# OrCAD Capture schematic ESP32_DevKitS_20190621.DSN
size C; title: ESP32-DevKitS-Board; rev: 0.1
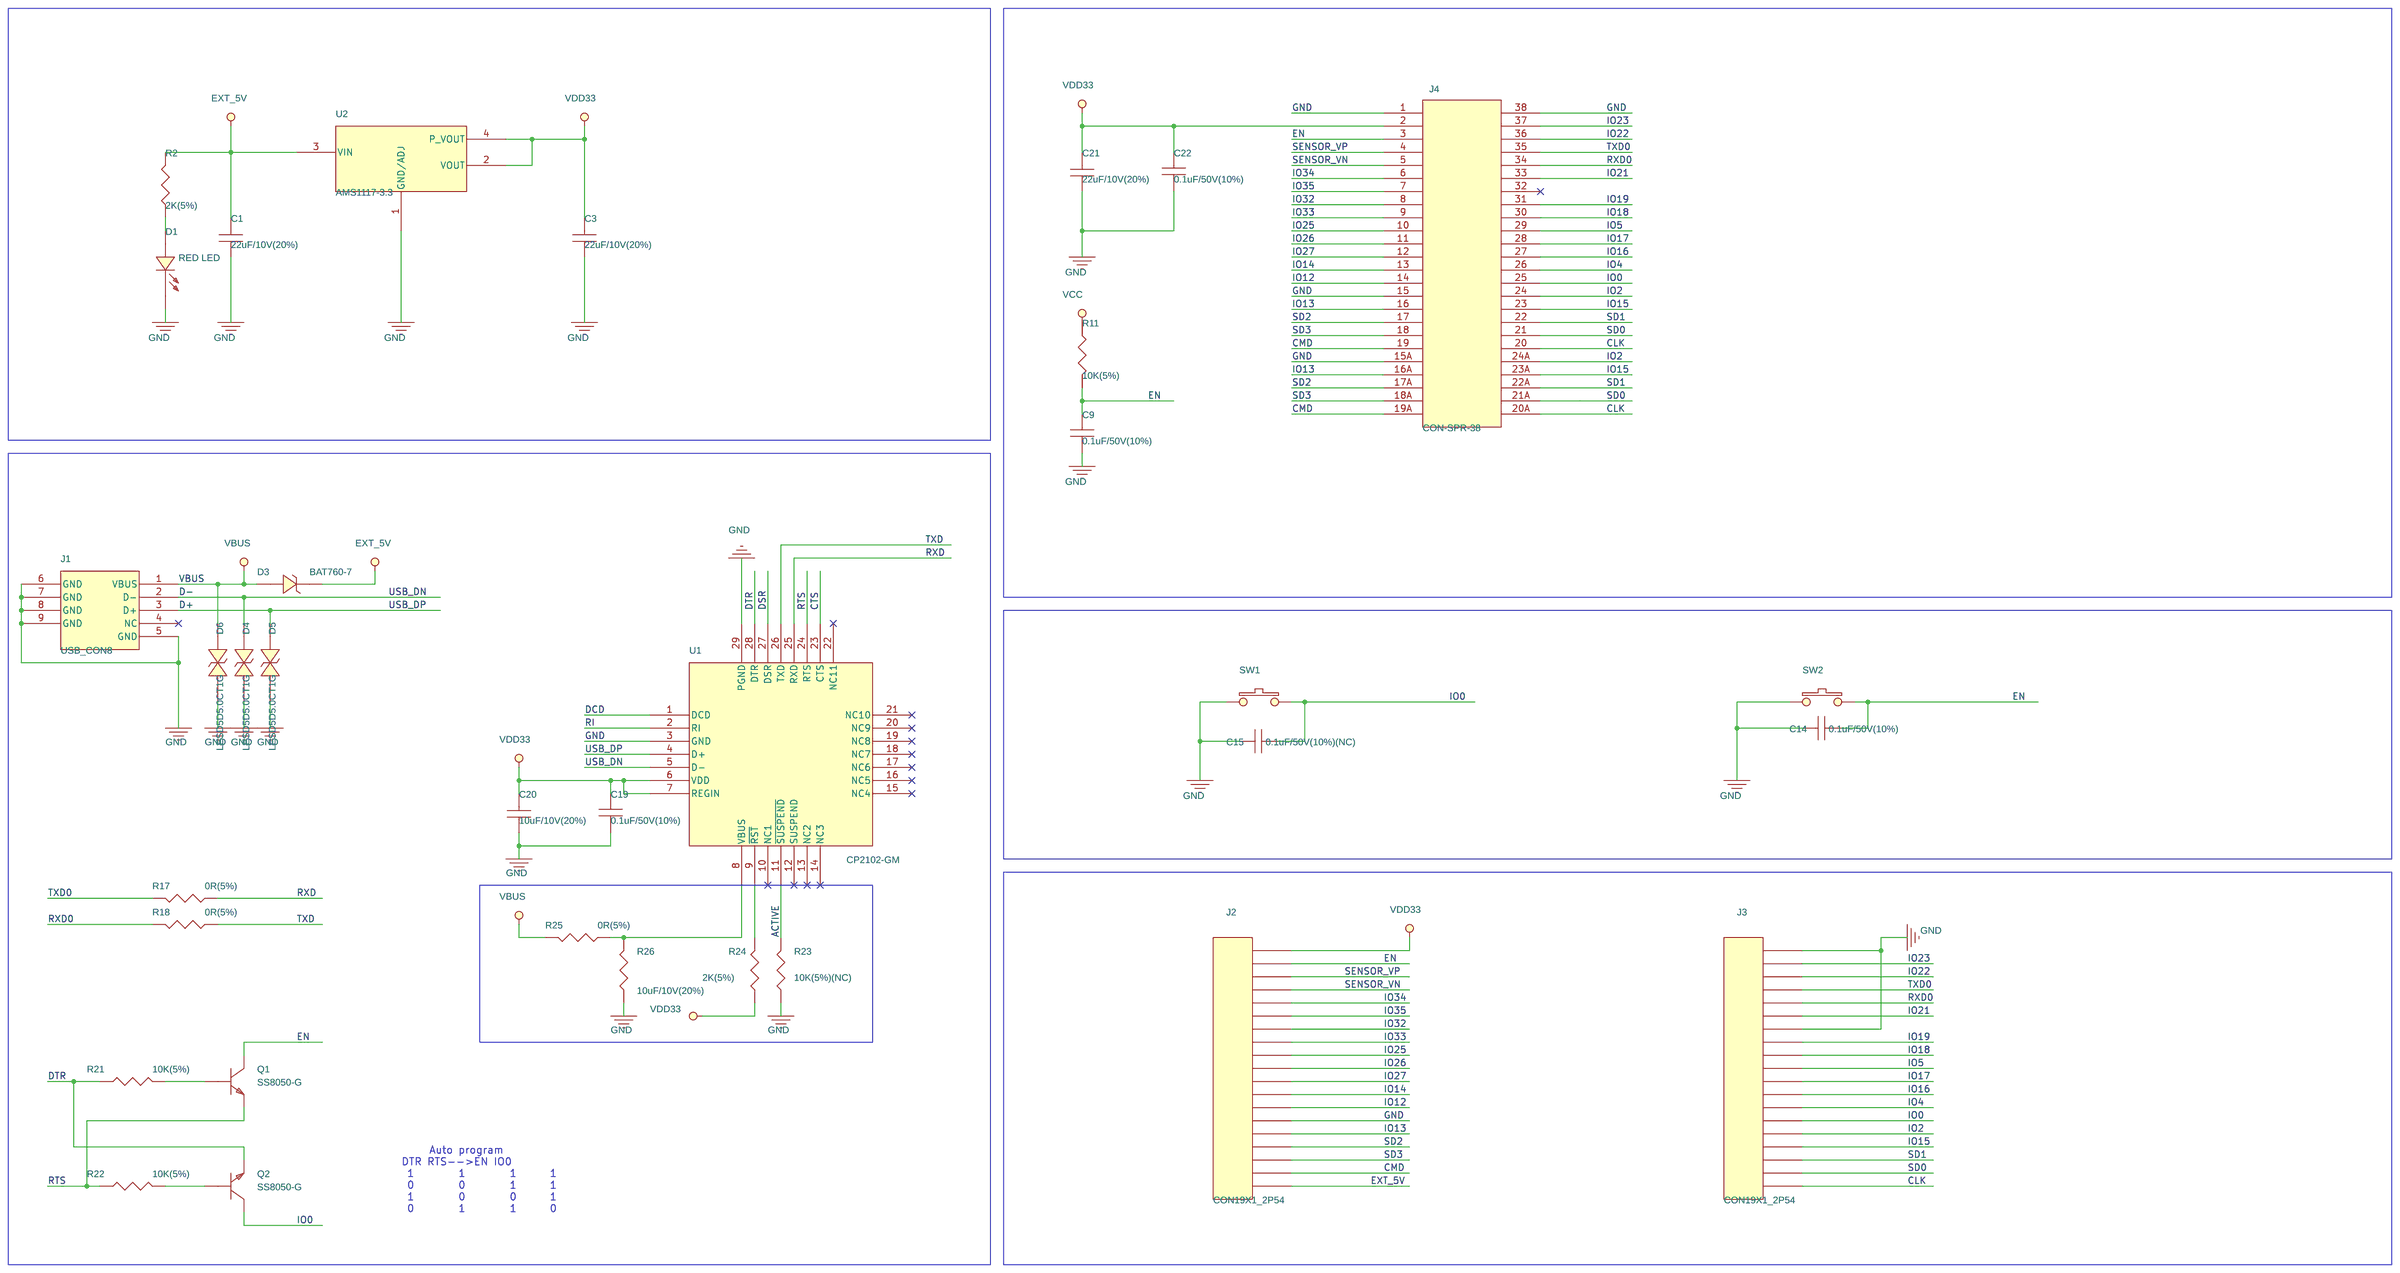
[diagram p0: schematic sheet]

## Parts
C1  22uF/10V(20%)  [C0603]
C3  22uF/10V(20%)  [C0603]
C9  0.1uF/50V(10%)  [C0402]
C14  0.1uF/50V(10%)  [C0402]
C15  0.1uF/50V(10%)(NC)  [C0402]
C19  0.1uF/50V(10%)  [C0402]
C20  10uF/10V(20%)  [C0402]
C21  22uF/10V(20%)  [C0603]
C22  0.1uF/50V(10%)  [C0402]
D1  RED LED  [0603D/A]
D3  BAT760-7  [SOD323]
D4  LESD5D5.0CT1G  [SOD-523]
D5  LESD5D5.0CT1G  [SOD-523]
D6  LESD5D5.0CT1G  [SOD-523]
J1  USB_CON8  [USB_5P]
J2  CON19X1_2P54  [CON19_2P54]
J3  CON19X1_2P54  [CON19_2P54]
J4  CON-SPR-38  [WROOM-32-SPR-17P5]
Q1  SS8050-G  [SOT-23-3]
Q2  SS8050-G  [SOT-23-3]
R2  2K(5%)  [R0402]
R11  10K(5%)  [R0402]
R17  0R(5%)  [R0402]
R18  0R(5%)  [R0402]
R21  10K(5%)  [R0402]
R22  10K(5%)  [R0402]
R23  10K(5%)(NC)  [R0402]
R24  2K(5%)  [R0402]
R25  0R(5%)  [R0402]
R26  10uF/10V(20%)  [R0402]
SW1  SW PUSHBUTTON  [SW_3X4X2MM]
SW2  SW PUSHBUTTON  [SW_3X4X2MM]
U1  CP2102-GM  [CP2102_QFN_28P]
U2  AMS1117-3.3  [SOT-223]

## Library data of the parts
C1 C3 C9 C14 C15 C19-C22 = CAP_NP
D1 = LED_1
D3 = DIODE_POWER_0
D4-D6 = DIODE_BI-DIR_TRIG: Options: ESD
J1 = CON4_2
J2 J3 = CON19_0
J4 = HEADER_9X2_3
Q1 Q2 = NPN_BCE_0
R2 R11 = RESISTOR_0
R17 R18 R25 = RESISTOR_0: SIGNAL_MODEL: DEFAULT_RESISTOR_10000OHM_1_2
R21-R24 R26 = RESISTOR_0: SIGNAL_MODEL: DEFAULT_RESISTOR_200OHM_1_2
SW1 SW2 = SW_PUSHBUTTON
U1 = CP2102_QFN_28
U2 = NCP1117_0

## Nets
GND: C1.1 C3.1 C9.2 C14.1 C15.1 C19.2 C20.1 C21.1 C22.2 D1.2(CATHODE) D4.2 D5.2 D6.2 J1.5(GND) J1.6(GND) J1.7(GND) J1.8(GND) J1.9(GND) J2.14 J3.1 J3.7 J4.1 J4.15 J4.15A J4.38 R23.1 R26.1 SW1.1 SW2.1 U1.3(GND) U1.29(PGND) U2.1(GND/ADJ)
VBUS: D3.2 D6.1 J1.1(VBUS) R25.2
VDD33: C3.2 C19.1 C20.2 C21.2 C22.1 J2.1 J4.2 R11.1 R24.1 U1.6(VDD) U1.7(REGIN) U2.2(VOUT) U2.4(P_VOUT)
ACTIVE: R23.2 U1.11(~{SUSPEND})
CLK: J3.19 J4.20 J4.20A
CMD: J2.18 J4.19 J4.19A
CTS: U1.23(CTS)
D+: D5.1 J1.3(D+) U1.4(D+)
D-: D4.1 J1.2(D-) U1.5(D-)
DCD: U1.1(DCD)
DSR: U1.27(DSR)
DTR: Q2.2(E) R21.1 U1.28(DTR)
EN: C9.1 C14.2 J2.2 J4.3 Q1.3(C) R11.2 SW2.2
EXT_5V: C1.2 D3.1 J2.19 R2.1 U2.3(VIN)
IO0: C15.2 J3.14 J4.25 Q2.3(C) SW1.2
IO2: J3.15 J4.24 J4.24A
IO4: J3.13 J4.26
IO5: J3.10 J4.29
IO12: J2.13 J4.14
IO13: J2.15 J4.16 J4.16A
IO14: J2.12 J4.13
IO15: J3.16 J4.23 J4.23A
IO16: J3.12 J4.27
IO17: J3.11 J4.28
IO18: J3.9 J4.30
IO19: J3.8 J4.31
IO21: J3.6 J4.33
IO22: J3.3 J4.36
IO23: J3.2 J4.37
IO25: J2.9 J4.10
IO26: J2.10 J4.11
IO27: J2.11 J4.12
IO32: J2.7 J4.8
IO33: J2.8 J4.9
IO34: J2.5 J4.6
IO35: J2.6 J4.7
RI: U1.2(RI)
RTS: Q1.2(E) R22.1 U1.24(RTS)
RXD: R17.1 U1.25(RXD)
RXD0: J3.5 J4.34 R18.2
SD0: J3.18 J4.21 J4.21A
SD1: J3.17 J4.22 J4.22A
SD2: J2.16 J4.17 J4.17A
SD3: J2.17 J4.18 J4.18A
SENSOR_VN: J2.4 J4.5
SENSOR_VP: J2.3 J4.4
TXD: R18.1 U1.26(TXD)
TXD0: J3.4 J4.35 R17.2
N16505834: Q2.1(B) R22.2
N16505838: Q1.1(B) R21.2
N16507634: R25.1 R26.2 U1.8(VBUS)
N16522975: D1.1(ANODE) R2.2
N16660617: R24.2 U1.9(~{RST})

Not connected (* = marked no-connect by the designer): J1 4(NC)*; J4 32*; U1 10(NC1)* 12(SUSPEND)* 13(NC2)* 14(NC3)* 15(NC4)* 16(NC5)* 17(NC6)* 18(NC7)* 19(NC8)* 20(NC9)* 21(NC10)* 22(NC11)*

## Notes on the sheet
- Auto program
  DTR RTS-->EN IO0
   1        1        1      1
   0        0        1      1
   1        0        0      1
   0        1        1      0
